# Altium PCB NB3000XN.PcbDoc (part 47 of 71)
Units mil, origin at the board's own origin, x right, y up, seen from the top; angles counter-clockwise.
Board outline 9527.56 x 6929.77 mil, 6 copper layers (Top Layer, GND+SHIELD, MidLayer1, MidLayer2, P2 - 3V3+5V0, Bottom Layer), stack 62.375 mil thick; 832 components, 1027 nets, 4655 pads, 4981 vias.
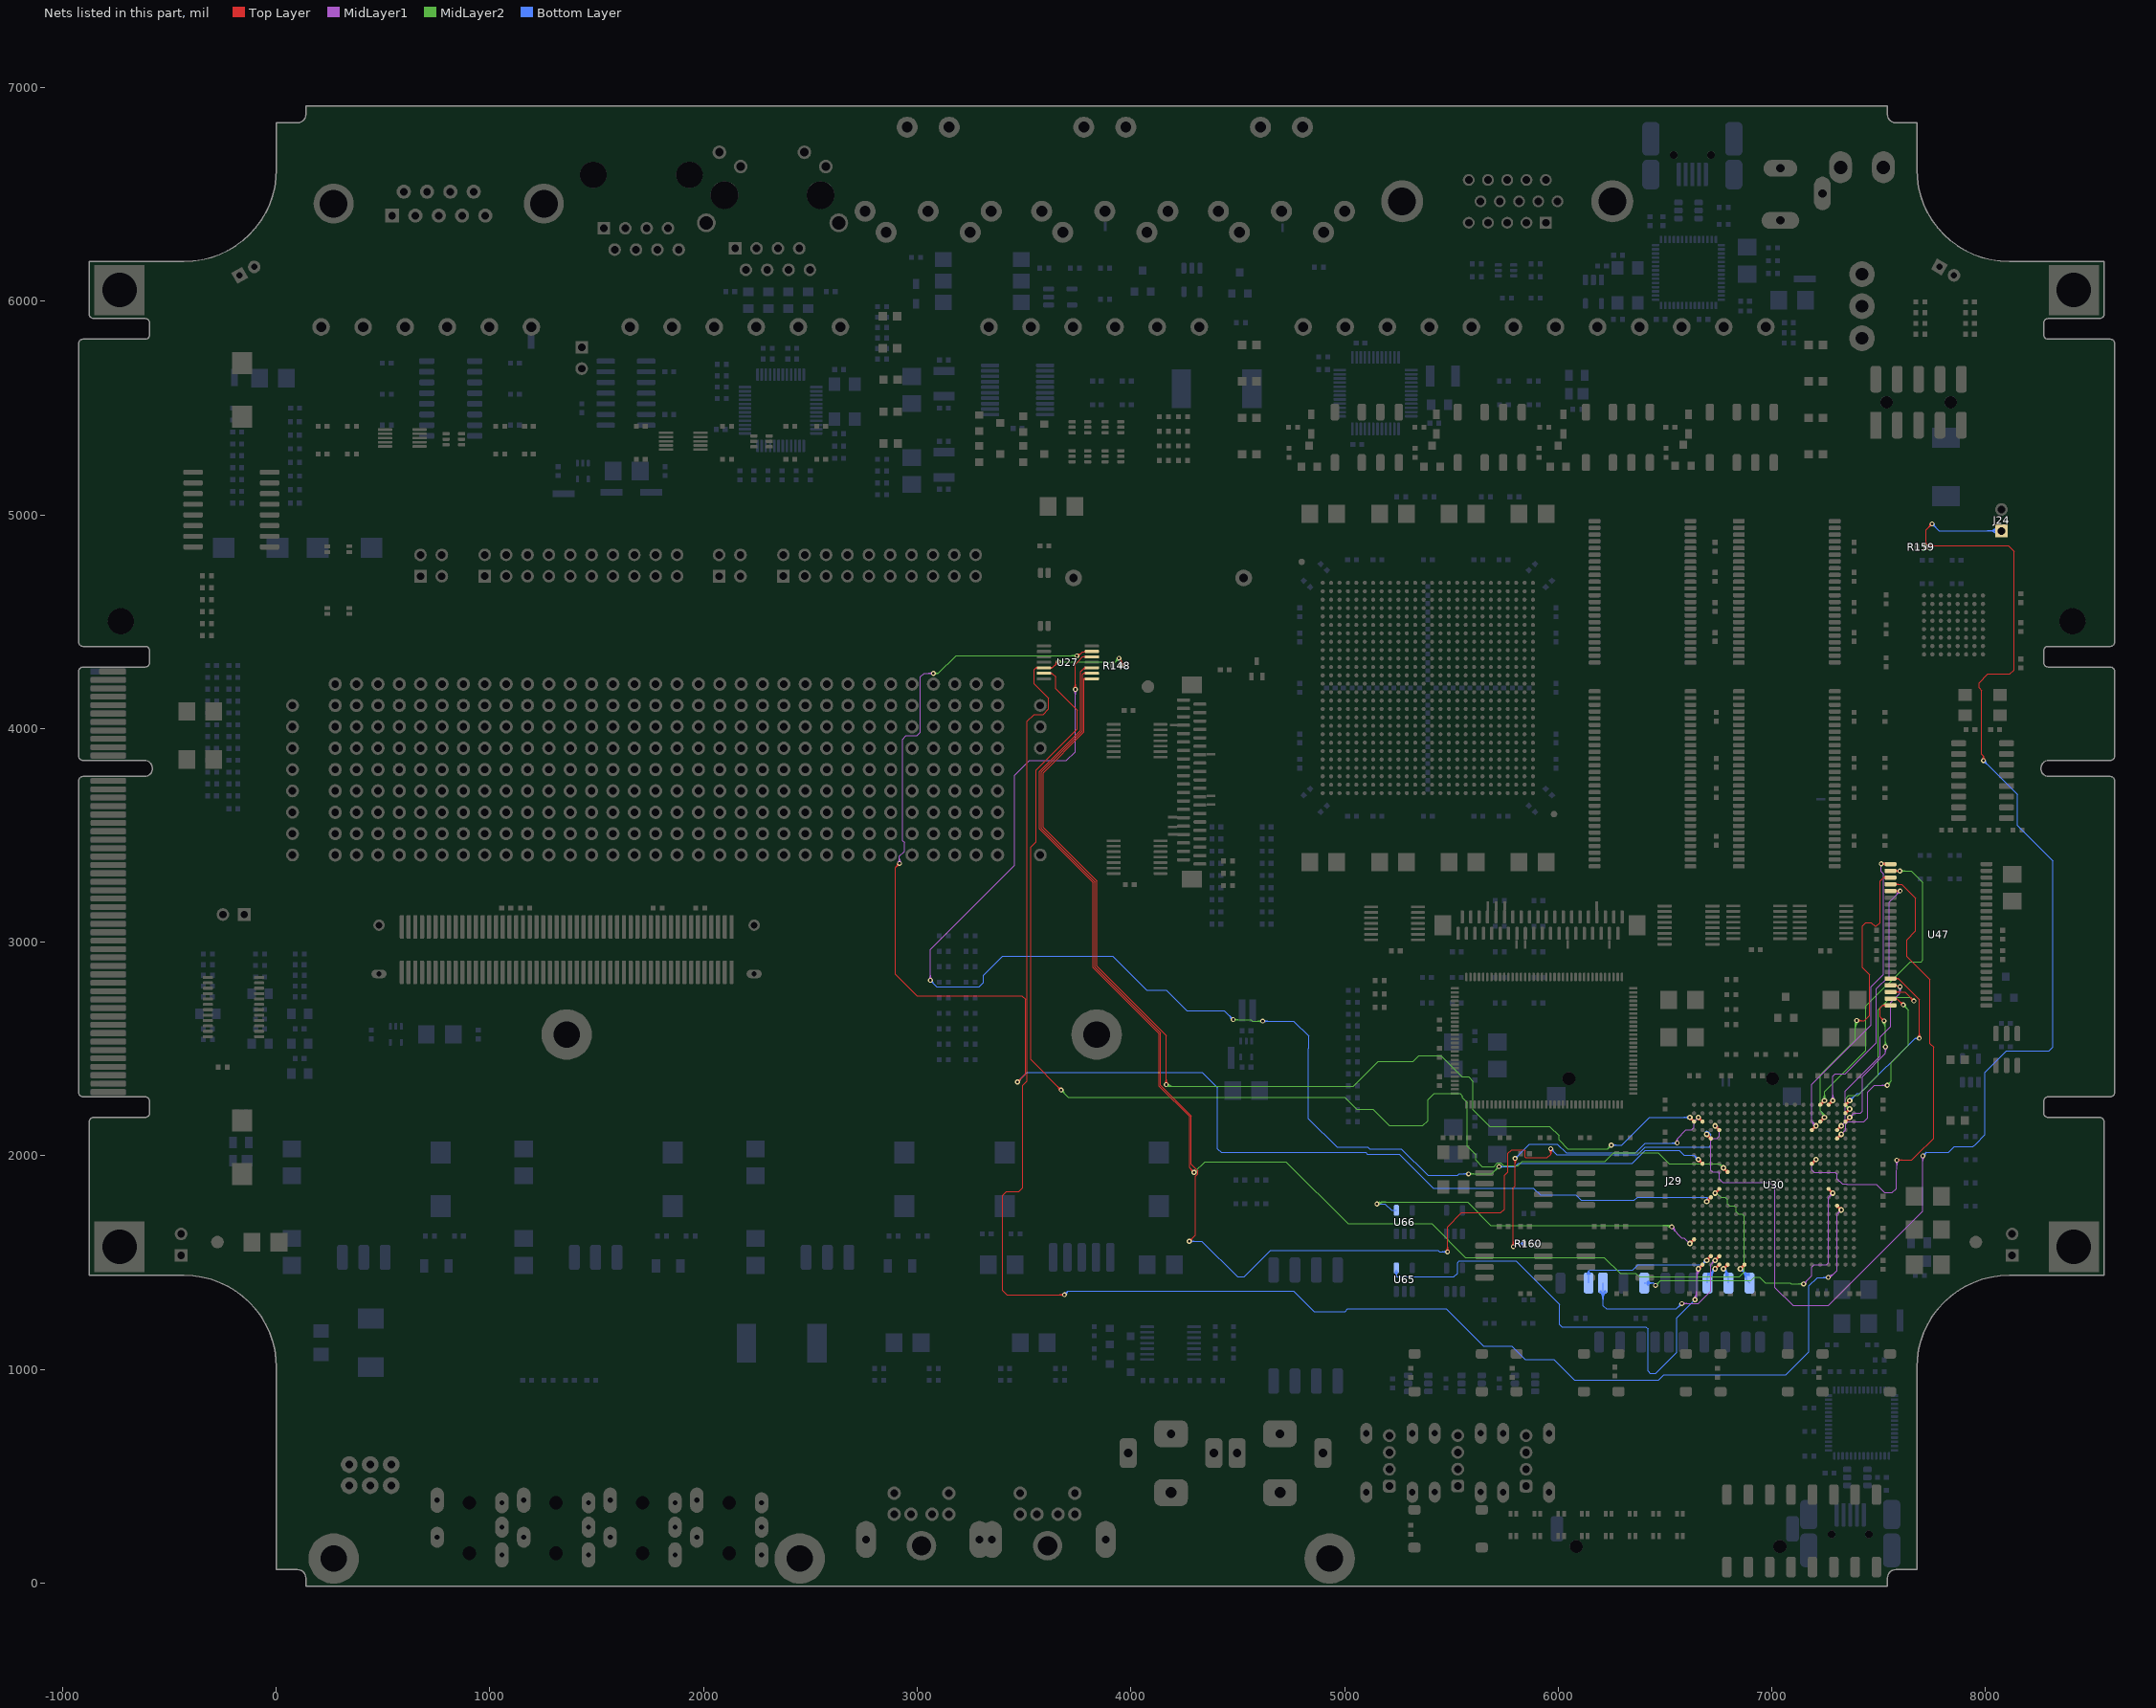
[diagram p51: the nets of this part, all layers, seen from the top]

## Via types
v1: diameter 23, hole 11.81, Top Layer to Bottom Layer, 3672 vias
v2: diameter 26, hole 11.81, Top Layer to Bottom Layer, 461 vias
v3: diameter 19, hole 11.81, Top Layer to Bottom Layer, tented both sides, 396 vias
v4: diameter 23.62, hole 11.81, Top Layer to Bottom Layer, 288 vias
v5: diameter 20, hole 11.81, Top Layer to Bottom Layer, 91 vias
v6: diameter 23, hole 11.81, Top Layer to Bottom Layer, tented both sides, 50 vias
v7: diameter 31, hole 11.81, Top Layer to Bottom Layer, 15 vias
v8: diameter 27.56, hole 11.81, Top Layer to Bottom Layer, tented both sides, 4 vias
v9: diameter 29, hole 11.81, Top Layer to Bottom Layer, 3 vias
v10: diameter 21, hole 11.81, Top Layer to Bottom Layer, 1 vias

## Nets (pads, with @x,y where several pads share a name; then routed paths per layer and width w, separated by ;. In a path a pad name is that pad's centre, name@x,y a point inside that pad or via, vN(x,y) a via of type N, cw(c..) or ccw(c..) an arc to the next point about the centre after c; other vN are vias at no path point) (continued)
HOST_M1: J24.1 R159.1 U30.U4 | length 7649.8
  Top Layer w4: R159.1@7714.59,4857.08 ccw(c7698.68,4872.99) 7721.18,4872.99 ccw(c7743.68,4872.99) R159.1@7727.77,4857.08 ; R159.1@7717.42,4854.25 ccw(c7708.34,4863.33) 7721.18,4863.33 ccw(c7734.02,4863.33) R159.1@7724.94,4854.25 ; R159.1@7722.11,4849.56 cw(c7740.08,4831.6) 7740.08,4857 ; R159.1@7724.94,4846.73 cw(c7749.73,4821.94) 7749.73,4857 ; R159.1@7727.77,4843.9 cw(c7759.39,4812.28) 7759.39,4857 ; v1@7740.69,4958.37 cw(c7717.76,4958.37) 7733.97,4942.16 cw(c7750.19,4925.94) v1@7750.19,4948.87 ; v1@7744.69,4958.37 cw(c7731.41,4958.37) 7740.8,4948.99 cw(c7750.19,4939.6) v1@7750.19,4952.87 ; v1(7750.19,4958.37) 7721.18,4929.37 R159.1@7721.18,4850 7728.18,4857 8107.71,4857 8135,4829.71 8135,4275 8115,4255 8011.82,4255 7970.52,4213.71 7970.52,4190 7981.86,4178.67 7981.86,3880 7990.19,3871.67 ; v1@7983.76,3857.04 ccw(c7970.33,3871.67) 7990.19,3871.67 ; v1@7986.47,3854.09 ccw(c7978.69,3862.56) 7990.19,3862.56 ccw(c8001.69,3862.56) v1@7993.91,3854.09 ; v1(7990.19,3850.04) 7990.19,3871.67 ; v1@7996.62,3857.04 cw(c8010.05,3871.67) 7990.19,3871.67
  Top Layer w8: v2@6734.41,2131.59 cw(c6734.41,2109.86) 6749.77,2125.23 cw(c6765.14,2140.59) v2@6743.41,2140.59 ; v2(6734.41,2140.59) U30.U4@6754.09,2120.91 ; U30.U4@6748.25,2120.91 ccw(c6734.15,2120.91) 6744.12,2130.88 ccw(c6754.09,2140.85) U30.U4@6754.09,2126.75
  MidLayer1 w4: v2@6734.41,2129.59 cw(c6734.41,2103.03) 6753.19,2121.81 cw(c6771.96,2140.59) v2@6745.41,2140.59 ; v2@6734.41,2133.59 cw(c6734.41,2116.69) 6746.36,2128.64 cw(c6758.31,2140.59) v2@6741.41,2140.59 ; v2(6734.41,2140.59) 6753.52,2121.48 6753.52,2091.71 6743.19,2081.37 6726.86,2081.37 6715.19,2069.71 6715.19,1932.37 6723.52,1924.04 6751.86,1924.04 6754.19,1921.71 6754.19,1891.71 6770.86,1875.04 6990.19,1875.04 7015.19,1850.04 7015.19,1383.37 7098.52,1300.04 7265.19,1300.04 7706.86,1741.71 v1(7706.86,2000.04) ; v1@7700.14,1993.32 cw(c7683.92,1977.11) 7706.86,1977.11 cw(c7729.79,1977.11) v1@7713.57,1993.32 ; v1@7702.97,1996.15 cw(c7693.58,1986.76) 7706.86,1986.76 cw(c7720.14,1986.76) v1@7710.75,1996.15
  Bottom Layer w4: v1(7706.86,2000.04) 7723.52,2016.71 7827.77,2016.71 7853.56,2042.5 7940.98,2042.5 7954.24,2055.76 7998.52,2100.04 7998.52,2391.71 8098.52,2491.71 8298.52,2491.71 8315.19,2508.37 8315.19,3380.39 8148.86,3546.73 8148.86,3691.37 8023.52,3816.71 v1(7990.19,3850.04) ; v1@7706.86,2005.54 ccw(c7706.86,2018.82) 7716.25,2009.43 ccw(c7725.64,2000.04) v1@7712.36,2000.04 ; v1@7706.86,2009.54 ccw(c7706.86,2032.48) 7723.07,2016.26 ccw(c7739.29,2000.04) v1@7716.36,2000.04 ; v1@7750.19,4948.87 cw(c7750.19,4925.94) 7766.41,4942.16 cw(c7782.63,4958.37) v1@7759.69,4958.37 ; v1@7750.19,4952.87 cw(c7750.19,4939.6) 7759.58,4948.99 cw(c7768.97,4958.37) v1@7755.69,4958.37 ; v1(7750.19,4958.37) 7783.19,4925.38 J24.1@8074.71,4925.38 ; v1@7990.19,3840.54 cw(c7990.19,3817.61) 8006.41,3833.82 cw(c8022.63,3850.04) v1@7999.69,3850.04 ; v1@7990.19,3844.54 cw(c7990.19,3831.26) 7999.58,3840.65 cw(c8008.97,3850.04) v1@7995.69,3850.04 ; J24.1@8055.24,4905.91 ccw(c8008.25,4858.92) 8008.25,4925.38 ccw(c8008.25,4991.84) J24.1@8055.24,4944.84 ; J24.1@8058.07,4908.74 ccw(c8017.91,4868.58) 8017.91,4925.38 ccw(c8017.91,4982.18) J24.1@8058.07,4942.01 ; J24.1@8060.9,4911.57 ccw(c8027.57,4878.23) 8027.57,4925.38 ccw(c8027.56,4972.52) J24.1@8060.9,4939.19 ; J24.1@8063.73,4914.4 ccw(c8037.22,4887.89) 8037.22,4925.38 ccw(c8037.22,4962.86) J24.1@8063.73,4936.36
HOST_M2: R160.1 U30.W3 | length 1865.2
  Top Layer w4: v1@5783.47,1581.76 ccw(c5767.26,1597.98) 5790.19,1597.98 ccw(c5813.13,1597.98) v1@5796.91,1581.76 ; v1@5786.3,1578.93 ccw(c5776.91,1588.32) 5790.19,1588.32 ccw(c5803.47,1588.32) v1@5794.08,1578.93 ; v1(5790.19,1575.04) 5790.19,1850.04 5798.52,1858.37 v1(5798.52,1988.04) ; v1@5791.81,1981.32 cw(c5775.59,1965.11) 5798.52,1965.11 cw(c5821.46,1965.11) v1@5805.24,1981.32 ; v1@5794.64,1984.15 cw(c5785.25,1974.76) 5798.52,1974.76 cw(c5811.8,1974.76) v1@5802.41,1984.15
  Top Layer w8: v2@6655.67,2170.96 cw(c6655.67,2149.23) 6671.03,2164.6 cw(c6686.4,2179.96) v2@6664.67,2179.96 ; v2(6655.67,2179.96) U30.W3@6675.35,2160.28 ; U30.W3@6669.51,2160.28 ccw(c6655.41,2160.28) 6665.38,2170.25 ccw(c6675.35,2180.22) U30.W3@6675.35,2166.12
  MidLayer1 w4: v1@6551.05,2067.56 ccw(c6541.94,2079.37) 6556.86,2079.37 ; v1(6556.86,2060.04) 6556.86,2079.37 ; v1@6562.66,2067.56 cw(c6571.78,2079.37) 6556.86,2079.37 ; v2(6655.67,2179.96) 6640.19,2164.48 6640.19,2163.48 6638.52,2161.82 6637.52,2161.82 6636.52,2160.82 6636.52,2133.37 6624.19,2121.04 6598.52,2121.04 6556.86,2079.37
  Bottom Layer w4: v1(5790.19,1575.04) 5805.15,1590 R160.1@5839.87,1590 ; v1(5798.52,1988.04) 5843.85,2033.36 5865.48,2055 5996.25,2055 6037.06,2014.19 6362.67,2014.19 6364.86,2016.37 6408.52,2060.04 v1(6556.86,2060.04) ; v1@5798.52,1993.54 ccw(c5798.52,2006.82) 5807.91,1997.43 ccw(c5817.3,1988.04) v1@5804.02,1988.04 ; v1@5798.52,1997.54 ccw(c5798.52,2020.48) 5814.74,2004.26 ccw(c5830.96,1988.04) v1@5808.02,1988.04 ; R160.1@5833.29,1583.41 ccw(c5817.38,1567.5) 5817.38,1590 ccw(c5817.38,1612.5) R160.1@5833.29,1596.59 ; R160.1@5836.11,1586.24 ccw(c5827.03,1577.16) 5827.03,1590 ccw(c5827.03,1602.84) R160.1@5836.11,1593.76 ; v1@6550.14,2053.32 ccw(c6533.92,2037.11) 6533.92,2060.04 ccw(c6533.92,2082.98) v1@6550.14,2066.76 ; v1@6552.97,2056.15 ccw(c6543.58,2046.76) 6543.58,2060.04 ccw(c6543.58,2073.32) v1@6552.97,2063.93
HOST_RTC.CLKOE: U27.12 U30.W8 | length 7212.1
  Top Layer w4: v1@3733.47,4190.09 ccw(c3717.26,4206.31) 3740.19,4206.31 ccw(c3763.13,4206.31) v1@3746.91,4190.09 ; v1@3736.3,4187.26 ccw(c3726.91,4196.65) 3740.19,4196.65 ccw(c3753.47,4196.65) v1@3744.08,4187.26 ; v1(3740.19,4183.37) 3740.19,4300.78 3754.62,4315.21 3775,4335.59 U27.12@3817.2,4335.59 ; U27.12@3787.17,4332.13 ccw(c3778.82,4323.79) 3778.82,4335.59 ccw(c3778.83,4347.39) U27.12@3787.17,4339.05
  Top Layer w8: v2@6655.67,1974.11 cw(c6655.67,1952.38) 6671.03,1967.75 cw(c6686.4,1983.11) v2@6664.67,1983.11 ; v2(6655.67,1983.11) U30.W8@6675.35,1963.43 ; U30.W8@6669.51,1963.43 ccw(c6655.41,1963.43) 6665.38,1973.4 ccw(c6675.35,1983.37) U30.W8@6675.35,1969.27
  MidLayer1 w4: v1@3054.81,2828.43 ccw(c3038.59,2844.64) 3061.52,2844.64 ccw(c3084.46,2844.64) v1@3068.24,2828.43 ; v1@3057.64,2825.6 ccw(c3048.25,2834.99) 3061.52,2834.99 ccw(c3074.8,2834.99) v1@3065.41,2825.6 ; v1(3061.52,2821.71) 3061.52,2966.02 3456.86,3361.36 3456.86,3781 3525.9,3850.04 3698.52,3850.04 3740.19,3891.71 v1(3740.19,4183.37) ; v1@3733.47,4176.66 cw(c3717.26,4160.44) 3740.19,4160.44 cw(c3763.13,4160.44) v1@3746.91,4176.66 ; v1@3736.3,4179.49 cw(c3726.91,4170.1) 3740.19,4170.1 cw(c3753.47,4170.1) v1@3744.08,4179.49
  MidLayer2 w4: v1(4478.86,2638.04) 4563,2638.04 4570,2631.04 v1(4616.86,2631.04) ; v1@4482.75,2634.15 cw(c4492.14,2624.76) 4492.14,2638.04 cw(c4492.14,2651.32) v1@4482.75,2641.93 ; v1@4485.57,2631.32 cw(c4501.79,2615.11) 4501.79,2638.04 cw(c4501.79,2660.98) v1@4485.57,2644.76 ; v1@4610.14,2624.32 ccw(c4593.92,2608.11) 4593.92,2631.04 ccw(c4593.92,2653.98) v1@4610.14,2637.76 ; v1@4612.97,2627.15 ccw(c4603.58,2617.76) 4603.58,2631.04 ccw(c4603.58,2644.32) v1@4612.97,2634.93 ; v1@5580.6,1913.79 v1(5580.6,1915.37) 5688.85,1915.37 v1(5723.52,1950.04) ; v1@5584.49,1911.48 cw(c5593.88,1902.09) 5593.88,1915.37 cw(c5593.88,1928.65) v1@5584.49,1919.26 ; v1@5587.32,1908.65 cw(c5603.54,1892.43) 5603.54,1915.37 cw(c5603.54,1938.3) v1@5587.32,1922.09 ; v1@5714.02,1950.04 cw(c5691.09,1950.04) 5707.31,1933.82 cw(c5723.52,1917.61) v1@5723.52,1940.54 ; v1@5718.02,1950.04 cw(c5704.75,1950.04) 5714.14,1940.65 cw(c5723.52,1931.26) v1@5723.52,1944.54
  Bottom Layer w4: v1@3061.52,2812.21 cw(c3061.52,2789.27) 3077.74,2805.49 cw(c3093.96,2821.71) v1@3071.02,2821.71 ; v1@3061.52,2816.21 cw(c3061.52,2802.93) 3070.91,2812.32 cw(c3080.3,2821.71) v1@3067.02,2821.71 ; v1(3061.52,2821.71) 3091.52,2791.71 3290.19,2791.71 3310.81,2812.32 3310.81,2845.81 3399.37,2934.37 3914.19,2934.37 4073.52,2775.04 4165.19,2775.04 4261.19,2679.04 4437.86,2679.04 v1(4478.86,2638.04) ; v1@4469.36,2638.04 ccw(c4446.42,2638.04) 4462.64,2654.26 ccw(c4478.86,2670.48) v1@4478.86,2647.54 ; v1@4473.36,2638.04 ccw(c4460.08,2638.04) 4469.47,2647.43 ccw(c4478.86,2656.82) v1@4478.86,2643.54 ; v1(4616.86,2631.04) 4761.56,2631.04 4832.19,2560.41 4832.19,2502.81 ; v1@4620.75,2627.15 cw(c4630.14,2617.76) 4630.14,2631.04 cw(c4630.14,2644.32) v1@4620.75,2634.93 ; v1@4623.57,2624.32 cw(c4639.79,2608.11) 4639.79,2631.04 cw(c4639.79,2653.98) v1@4623.57,2637.76 ; 4831.86,2502.81 4831.86,2174.04 4964.19,2041.71 5108.19,2041.71 5116.52,2033.37 5266.15,2033.37 5391.15,1908.37 5530,1908.37 5536.99,1915.37 v1(5580.6,1915.37) v1@5580.6,1913.79 ; v1@5573.88,1908.65 ccw(c5557.67,1892.43) 5557.67,1915.37 ccw(c5557.67,1938.3) v1@5573.88,1922.09 ; v1@5576.71,1911.48 ccw(c5567.32,1902.09) 5567.32,1915.37 ccw(c5567.32,1928.65) v1@5576.71,1919.26 ; v1(5723.52,1950.04) 5798.52,1950.04 5814.52,1966.04 6347.86,1966.04 6406.86,2025.04 6567.52,2025.04 6589.86,2002.71 6636.07,2002.71 v2(6655.67,1983.11) ; v1@5727.41,1946.15 cw(c5736.8,1936.76) 5736.8,1950.04 cw(c5736.8,1963.32) v1@5727.41,1953.93 ; v1@5730.24,1943.32 cw(c5746.46,1927.11) 5746.46,1950.04 cw(c5746.46,1972.98) v1@5730.24,1956.76 ; v2@6644.67,1983.11 ccw(c6618.11,1983.11) 6636.89,2001.89 ccw(c6655.67,2020.67) v2@6655.67,1994.11 ; v2@6648.67,1983.11 ccw(c6631.77,1983.11) 6643.72,1995.06 ccw(c6655.67,2007.01) v2@6655.67,1990.11
HOST_RTC.CLKOUT: U27.13 U30.V12 | length 7676.6
  Top Layer w4: v1@2907.69,3368.71 cw(c2884.76,3368.71) 2900.97,3352.49 cw(c2917.19,3336.27) v1@2917.19,3359.21 ; v1@2911.69,3368.71 cw(c2898.41,3368.71) 2907.8,3359.32 cw(c2917.19,3349.93) v1@2917.19,3363.21 ; v1(2917.19,3368.71) 2898.52,3350.04 2898.52,2850.04 2999.02,2749.54 3490.46,2749.54 3507.19,2732.81 3507.19,2383.71 v1(3469.52,2346.04) ; v1@3469.52,2351.54 ccw(c3469.52,2364.82) 3478.91,2355.43 ccw(c3488.3,2346.04) v1@3475.02,2346.04 ; v1@3469.52,2355.54 ccw(c3469.52,2378.48) 3485.74,2362.26 ccw(c3501.96,2346.04) v1@3479.02,2346.04 ; v1(3747.52,4340.37) 3755.52,4340.37 3773.52,4358.37 ; v1@3747.71,4341.86 ccw(c3749.78,4358.89) 3761.91,4346.76 ; v1@3748.19,4345.83 ccw(c3751.04,4369.24) 3767.72,4352.57 ; v1@3748.67,4349.81 ccw(c3752.3,4379.59) 3773.52,4358.37 ; 3782.42,4358.37 ccw(c3782.42,4368.46) U27.13@3789.96,4361.77 ; U27.13@3786.97,4364.42 cw(c3773.53,4376.34) 3773.53,4358.37 ; U27.13@3817.2,4361.18 3790.63,4361.17 3790.63,4358.37 3773.52,4358.37
  Top Layer w8: v2(6695.04,1786.26) U30.V12@6714.72,1805.94 ; v2@6695.04,1795.26 ccw(c6695.04,1816.99) 6710.4,1801.62 ccw(c6725.77,1786.26) v2@6704.04,1786.26 ; U30.V12@6708.88,1805.94 cw(c6694.78,1805.94) 6704.75,1795.97 cw(c6714.72,1786) U30.V12@6714.72,1800.1
  MidLayer1 w4: v1@2910.47,3375.43 ccw(c2894.26,3391.64) 2917.19,3391.64 ccw(c2940.13,3391.64) v1@2923.91,3375.43 ; v1@2913.3,3372.6 ccw(c2903.91,3381.99) 2917.19,3381.99 ccw(c2930.47,3381.99) v1@2921.08,3372.6 ; v1(2917.19,3368.71) 2917.19,3402.04 2940.19,3425.04 2940.19,3466.71 2931.86,3475.04 2931.86,3950.04 2948.52,3966.71 2998.52,3966.71 3015.19,3983.37 3015.19,4241.71 3031.86,4258.37 v1(3075.86,4258.37) ; v1@3069.14,4251.66 ccw(c3052.92,4235.44) 3052.92,4258.37 ccw(c3052.92,4281.31) v1@3069.14,4265.09 ; v1@3071.97,4254.49 ccw(c3062.58,4245.1) 3062.58,4258.37 ccw(c3062.58,4271.65) v1@3071.97,4262.26
  MidLayer2 w4: v1(3075.86,4258.37) 3098.52,4258.37 ; v1@3079.78,4254.52 cw(c3088.98,4245.47) 3088.98,4258.37 cw(c3088.98,4271.28) v1@3079.78,4262.23 ; v1@3082.63,4251.71 cw(c3098.52,4236.09) 3098.52,4258.37 ; v1@3082.63,4265.04 ccw(c3098.52,4280.66) 3098.52,4258.37 ; 3721.37,4341.71 cw(c3721.37,4314.22) v1@3740.81,4333.66 ; 3727.81,4341.71 ccw(c3727.81,4360.09) v1@3740.81,4347.09 ; 3731.03,4341.71 cw(c3731.03,4323.88) v1@3743.64,4336.49 ; v1(3747.52,4340.37) 3746.19,4341.71 3181.86,4341.71 3098.52,4258.37
  Bottom Layer w4: v1(3469.52,2346.04) 3515.19,2391.71 4334.84,2391.71 4406.52,2320.02 4406.52,2033.16 4422.98,2016.71 5099.25,2016.71 5107.25,2008.71 5256.52,2008.71 5277.07,1988.16 5415.52,1849.71 5883.17,1849.71 5916.17,1816.71 6081.86,1816.71 6106.86,1791.71 6356.86,1791.71 6371.52,1806.37 6696.86,1806.37 6698.52,1804.71 ; v1@3469.52,2351.54 ccw(c3469.52,2364.82) 3478.91,2355.43 ccw(c3488.3,2346.04) v1@3475.02,2346.04 ; v1@3469.52,2355.54 ccw(c3469.52,2378.48) 3485.74,2362.26 ccw(c3501.96,2346.04) v1@3479.02,2346.04 ; v2@6692.43,1796.95 ccw(c6690.53,1804.71) 6698.52,1804.71 ; v2@6693.38,1793.06 ccw(c6691.78,1799.61) 6698.52,1799.61 ; v2(6695.04,1786.26) 6698.52,1786.26 6698.52,1804.71 ; 6698.52,1804.4 ccw(c6713.18,1804.4) v2@6702.82,1794.04
HOST_RTC.CS_N: U27.6 U30.T9 | length 6107.5
  Top Layer w4: U27.6@3592.8,4258.82 3631.41,4258.82 3648.52,4241.71 3648.52,4186.73 3749.19,4086.06 3749.19,3998.34 3557.19,3806.34 3557.19,3470.33 3531.86,3445 3531.86,2450.04 v1(3673.52,2308.37) ; U27.6@3622.83,4255.36 cw(c3631.17,4247.01) 3631.17,4258.82 cw(c3631.18,4270.62) U27.6@3622.83,4262.28 ; v1@3664.02,2308.37 ccw(c3641.09,2308.37) 3657.31,2324.59 ccw(c3673.52,2340.81) v1@3673.52,2317.87 ; v1@3668.02,2308.37 ccw(c3654.75,2308.37) 3664.14,2317.76 ccw(c3673.52,2327.15) v1@3673.52,2313.87
  Top Layer w8: v2@6773.78,1934.74 cw(c6773.78,1913.01) 6789.14,1928.38 cw(c6804.51,1943.74) v2@6782.78,1943.74 ; v2(6773.78,1943.74) U30.T9@6793.46,1924.06 ; U30.T9@6787.62,1924.06 ccw(c6773.52,1924.06) 6783.49,1934.03 ccw(c6793.46,1944) U30.T9@6793.46,1929.9
  MidLayer2 w4: v1@3673.52,2298.87 cw(c3673.52,2275.94) 3689.74,2292.16 cw(c3705.96,2308.37) v1@3683.02,2308.37 ; v1@3673.52,2302.87 cw(c3673.52,2289.6) 3682.91,2298.99 cw(c3692.3,2308.37) v1@3679.02,2308.37 ; v1(3673.52,2308.37) 3707.19,2274.71 5001.84,2274.71 5057.53,2219.02 5132.88,2219.02 5210.19,2141.71 5366.9,2141.71 5390.19,2165 5390.19,2263.04 5418.86,2291.71 5540.19,2291.71 5552.19,2279.71 5552.19,2272.62 5575,2249.81 5575,2045 5614.02,2005.98 5614.02,1980 5644.02,1950 5698.73,1950 5716.28,1967.54 5730.77,1967.54 5743.77,1954.54 5812.4,1954.54 5831.57,1973.71 6219.57,1973.71 6260.05,2014.19 6467.71,2014.19 6518.86,1963.04 6754.48,1963.04 v2(6773.78,1943.74) ; v2@6762.78,1943.74 ccw(c6736.22,1943.74) 6755,1962.52 ccw(c6773.78,1981.3) v2@6773.78,1954.74 ; v2@6766.78,1943.74 ccw(c6749.88,1943.74) 6761.83,1955.69 ccw(c6773.78,1967.64) v2@6773.78,1950.74
HOST_RTC.DIN: U27.9 U30.V5 | length 6833.9
  Top Layer w4: U27.9@3787.17,4255.36 ccw(c3778.83,4247.01) 3778.83,4258.82 ; U27.9@3787.17,4262.28 cw(c3778.82,4270.62) 3778.82,4258.82 ; U27.9@3817.2,4258.82 3778.82,4258.82 ; v1(4273.52,1600.04) 4303.2,1629.72 4303.2,1905.16 4313.46,1915.41 4313.46,1929.91 4282.52,1960.84 4282.52,2187.48 4140,2330 4140,2575.9 3832,2883.9 3832,3282.56 3581.19,3533.37 3581.19,3796.39 3773.52,3988.73 3773.52,4253.52 3778.82,4258.82 ; v1@4273.52,1605.54 ccw(c4273.52,1618.82) 4282.91,1609.43 ccw(c4292.3,1600.04) v1@4279.02,1600.04 ; v1@4273.52,1609.54 ccw(c4273.52,1632.48) 4289.74,1616.26 ccw(c4305.96,1600.04) v1@4283.02,1600.04 ; v1(5481.86,1550.04) 5481.86,1666.71 5548.52,1733.37 5731.86,1733.37 5748.52,1750.04 5748.52,1908.37 5765.19,1925.04 5765.19,2011.71 5781.86,2028.37 5843.86,2028.37 5845.52,2026.71 5845.52,1993.37 5847.19,1991.71 5948.52,1991.71 5965.19,2008.37 v1(5965.19,2033.37) ; v1@5958.47,2026.66 cw(c5942.26,2010.44) 5965.19,2010.44 cw(c5988.13,2010.44) v1@5971.91,2026.66 ; v1@5961.3,2029.49 cw(c5951.91,2020.1) 5965.19,2020.1 cw(c5978.47,2020.1) v1@5969.08,2029.49 ; 5481.86,1563.32 cw(c5468.58,1563.32) 5477.97,1553.93 ccw(c5468.58,1563.32) 5481.86,1563.32 ; 5481.86,1563.32 ccw(c5495.14,1563.32) 5485.75,1553.93 cw(c5495.14,1563.32) 5481.86,1563.32 ; 5481.86,1572.98 cw(c5458.92,1572.98) 5475.14,1556.76 ccw(c5458.92,1572.98) 5481.86,1572.98 ; 5481.86,1572.98 ccw(c5504.79,1572.98) 5488.57,1556.76 cw(c5504.79,1572.98) 5481.86,1572.98
  Top Layer w8: v2@6695.04,2092.22 cw(c6695.04,2070.49) 6710.4,2085.86 cw(c6725.77,2101.22) v2@6704.04,2101.22 ; v2(6695.04,2101.22) U30.V5@6714.72,2081.54 ; U30.V5@6708.88,2081.54 ccw(c6694.78,2081.54) 6704.75,2091.51 ccw(c6714.72,2101.48) U30.V5@6714.72,2087.38
  Bottom Layer w4: v1(4273.52,1600.04) 4331.86,1600.04 4498.52,1433.37 4530,1433.37 4600.69,1504.06 4653.63,1557 5438,1557 5444.96,1550.04 v1(5481.86,1550.04) ; v1@4277.41,1596.15 cw(c4286.8,1586.76) 4286.8,1600.04 cw(c4286.8,1613.32) v1@4277.41,1603.93 ; v1@4280.24,1593.32 cw(c4296.46,1577.11) 4296.46,1600.04 cw(c4296.46,1622.98) v1@4280.24,1606.76 ; v1@5475.14,1543.32 ccw(c5458.92,1527.11) 5458.92,1550.04 ccw(c5458.92,1572.98) v1@5475.14,1556.76 ; v1@5477.97,1546.15 ccw(c5468.58,1536.76) 5468.58,1550.04 ccw(c5468.58,1563.32) v1@5477.97,1553.93 ; v1@5965.19,2023.87 cw(c5965.19,2000.94) 5981.41,2017.16 cw(c5997.63,2033.37) v1@5974.69,2033.37 ; v1@5965.19,2027.87 cw(c5965.19,2014.6) 5974.58,2023.99 cw(c5983.97,2033.37) v1@5970.69,2033.37 ; v1(5965.19,2033.37) 5992.38,2006.19 6371.34,2006.19 6406.86,2041.71 6706.86,2041.71 6715.19,2050.04 6715.19,2100.04 6706.86,2108.37 6695.04,2108.37 v2(6695.04,2101.22) ; 6687.37,2111.71 cw(c6695.33,2100.82) 6704.87,2110.36 ; v2@6689.73,2108.49 cw(c6698.12,2097.01) 6708.17,2107.06 ; v2@6692.09,2105.26 cw(c6700.91,2093.2) 6711.47,2103.76 ; v2@6694.45,2102.03 cw(c6703.7,2089.38) 6714.77,2100.46
HOST_RTC.DOUT: U27.8 U30.Y3 | length 5564
  Top Layer w4: U27.8@3786.55,4230.53 ccw(c3781.52,4227.19) 3781.52,4233.23 ; U27.8@3786.55,4235.93 cw(c3781.52,4239.26) 3781.52,4233.23 ; U27.8@3817.2,4233.23 3781.52,4233.23 ; 3840,3205 3840,3285.88 3589.19,3536.69 3589.19,3793.08 3781.52,3985.41 3781.52,4233.23 ; 3840.19,3205 3840.19,2887.02 4165.19,2562.02 v1(4165.19,2333.37) ; v1@4158.47,2340.09 ccw(c4142.26,2356.31) 4165.19,2356.31 ccw(c4188.13,2356.31) v1@4171.91,2340.09 ; v1@4161.3,2337.26 ccw(c4151.91,2346.65) 4165.19,2346.65 ccw(c4178.47,2346.65) v1@4169.08,2337.26
  Top Layer w8: v2@6616.3,2170.96 cw(c6616.3,2149.23) 6631.66,2164.6 cw(c6647.03,2179.96) v2@6625.3,2179.96 ; v2(6616.3,2179.96) U30.Y3@6635.98,2160.28 ; U30.Y3@6630.14,2160.28 ccw(c6616.04,2160.28) 6626.01,2170.25 ccw(c6635.98,2180.22) U30.Y3@6635.98,2166.12
  MidLayer2 w4: v1@4163.42,2331.61 ccw(c4179.27,2347.46) 4179.27,2325.04 ; v1(4165.19,2333.37) 4173.52,2325.04 5041.35,2325.04 5158.02,2441.71 5321.52,2441.71 5348.52,2468.71 5451.29,2468.71 5550,2370 5580,2370 5602.19,2347.81 5602.19,2275 ; v1@4166.25,2334.44 ccw(c4188.93,2357.12) 4188.93,2325.04 ; v1@4169.08,2337.26 ccw(c4198.59,2366.77) 4198.59,2325.04 ; v1@4171.91,2340.09 ccw(c4208.25,2376.43) 4208.25,2325.04 ; 5602.19,2290 5602.19,2275 ; v1@6239.02,2050.04 cw(c6216.09,2050.04) 6232.31,2033.82 cw(c6248.52,2017.61) v1@6248.52,2040.54 ; v1@6243.02,2050.04 cw(c6229.75,2050.04) 6239.13,2040.65 cw(c6248.52,2031.26) v1@6248.52,2044.54 ; v1(6248.52,2050.04) 6231.86,2033.37 6045.56,2033.37 6004.5,2074.44 6004.5,2094.06 5960.19,2138.37 5678.81,2138.37 5602.19,2215 5602.19,2275
  Bottom Layer w4: v1(6248.52,2050.04) 6298.52,2050.04 6428.44,2179.96 v2(6616.3,2179.96) ; v1@6252.41,2046.15 cw(c6261.8,2036.76) 6261.8,2050.04 cw(c6261.8,2063.32) v1@6252.41,2053.93 ; v1@6255.24,2043.32 cw(c6271.46,2027.11) 6271.46,2050.04 cw(c6271.46,2072.98) v1@6255.24,2056.76 ; v2@6608.52,2172.18 ccw(c6589.74,2153.4) 6589.74,2179.96 ccw(c6589.74,2206.52) v2@6608.52,2187.74 ; v2@6611.35,2175.01 ccw(c6599.4,2163.06) 6599.4,2179.96 ccw(c6599.4,2196.86) v2@6611.35,2184.91
HOST_RTC.INT_N: R148.2 U27.5 U30.C13 | length 8985.1
  Top Layer w4: U27.5@3562.29,4281.5 ccw(c3556.52,4277.24) 3556.52,4284.41 ; U27.5@3562.29,4287.32 cw(c3556.52,4291.58) 3556.52,4284.41 ; U27.5@3622.83,4280.95 cw(c3631.17,4272.61) 3631.17,4284.41 cw(c3631.18,4296.22) U27.5@3622.83,4287.87 ; v1@3652.02,4312.37 cw(c3629.09,4312.37) 3645.31,4296.16 cw(c3661.52,4279.94) v1@3661.52,4302.87 ; v1@3656.02,4312.37 cw(c3642.75,4312.37) 3652.14,4302.99 cw(c3661.52,4293.6) v1@3661.52,4306.87 ; v1(3661.52,4312.37) 3633.56,4284.41 3556.52,4284.41 ; v1@3682.47,1343.32 ccw(c3666.26,1327.11) 3666.26,1350.04 ccw(c3666.26,1372.98) v1@3682.47,1356.76 ; v1@3685.3,1346.15 ccw(c3675.91,1336.76) 3675.91,1350.04 ccw(c3675.91,1363.32) v1@3685.3,1353.93 ; v1(3689.19,1350.04) 3419.96,1350.04 3400,1370 3400,1815 3418,1833 3476.69,1833 3495,1851.31 3495,2329.81 3515.19,2350 3515.19,4033.37 3548.52,4066.71 3590.19,4066.71 3615.19,4091.71 3615.19,4141.71 3548.52,4208.37 3548.52,4276.41 3556.52,4284.41 ; v1(3944.52,4329.37) 3956.18,4317.72 ; R148.2@3949.65,4302.14 ccw(c3934.34,4317.72) 3956.18,4317.72 ; R148.2@3952.45,4299.29 ccw(c3943.71,4308.18) 3956.18,4308.18 ccw(c3968.65,4308.18) R148.2@3959.91,4299.29 ; R148.2@3956.18,4295 3956.18,4317.72 ; R148.2@3962.71,4302.14 cw(c3978.02,4317.72) 3956.18,4317.72
  Top Layer w8: U30.C13@7305.28,1760.73 cw(c7305.28,1746.63) 7315.25,1756.6 cw(c7325.22,1766.57) U30.C13@7311.12,1766.57 ; U30.C13@7305.28,1766.57 v2(7324.96,1746.89) ; v2@7315.96,1746.89 ccw(c7294.23,1746.89) 7309.6,1762.25 ccw(c7324.96,1777.62) v2@7324.96,1755.89
  MidLayer1 w4: v1(7263.86,1431.04) 7272.2,1431.04 7305,1463.84 7305,1726.93 v2(7324.96,1746.89) ; v1@7263.86,1432.54 ccw(c7263.86,1456.31) 7280.66,1439.5 ; v1@7263.86,1436.54 ccw(c7263.86,1469.97) 7287.49,1446.33 ; v1@7263.86,1440.54 ccw(c7263.86,1483.62) 7294.32,1453.16 ; v2@7313.96,1746.89 cw(c7287.4,1746.89) 7306.18,1728.11 cw(c7324.96,1709.33) v2@7324.96,1735.89 ; v2@7317.96,1746.89 cw(c7301.06,1746.89) 7313.01,1734.94 cw(c7324.96,1722.99) v2@7324.96,1739.89
  MidLayer2 w4: v1(3661.52,4312.37) 3927.52,4312.37 v1(3944.52,4329.37) ; v1@3665.41,4308.49 cw(c3674.8,4299.1) 3674.8,4312.37 cw(c3674.8,4325.65) v1@3665.41,4316.26 ; v1@3668.24,4305.66 cw(c3684.46,4289.44) 3684.46,4312.37 cw(c3684.46,4335.31) v1@3668.24,4319.09 ; v1@3935.02,4329.37 cw(c3912.09,4329.37) 3928.31,4313.16 cw(c3944.52,4296.94) v1@3944.52,4319.87 ; v1@3939.02,4329.37 cw(c3925.75,4329.37) 3935.14,4319.99 cw(c3944.52,4310.6) v1@3944.52,4323.87
  Bottom Layer w4: v1(3689.19,1350.04) 3706.19,1367.04 4761.88,1367.04 4856.92,1272 5003.31,1272 5014.69,1283.37 5475.9,1283.37 5650.27,1109 5783.6,1109 5838.8,1053.8 5845.6,1047 5979.56,1047 6076.52,950.04 6469.82,950.04 6494.82,975.04 7065.04,975.04 7173.52,1083.52 7173.52,1391.71 7212.86,1431.04 v1(7263.86,1431.04) ; v1@3689.19,1355.54 ccw(c3689.19,1368.82) 3698.58,1359.43 ccw(c3707.97,1350.04) v1@3694.69,1350.04 ; v1@3689.19,1359.54 ccw(c3689.19,1382.48) 3705.41,1366.26 ccw(c3721.63,1350.04) v1@3698.69,1350.04 ; v1@7257.14,1424.32 ccw(c7240.92,1408.11) 7240.92,1431.04 ccw(c7240.92,1453.98) v1@7257.14,1437.76 ; v1@7259.97,1427.15 ccw(c7250.58,1417.76) 7250.58,1431.04 ccw(c7250.58,1444.32) v1@7259.97,1434.93
HOST_RTC.SCLK: U27.10 U30.U11 | length 6377.7
  Top Layer w4: 3769.07,4270.59 cw(c3790.63,4249.03) U27.10@3790.63,4279.52 ; 3775.9,4277.42 cw(c3790.63,4262.69) U27.10@3790.63,4283.52 ; 3777.99,4279.51 cw(c3783.45,4274.05) U27.10@3787.84,4280.39 ; 3781.38,4282.89 cw(c3786.22,4278.05) U27.10@3790.12,4283.68 ; 3782.73,4284.25 cw(c3790.63,4276.35) U27.10@3790.63,4287.52 ; U27.10@3786.09,4286.24 cw(c3781.86,4287.94) 3781.86,4283.37 ; U27.10@3787.03,4281.1 ccw(c3781.86,4276.36) 3781.86,4283.37 ; U27.10@3817.2,4284.41 3823.52,4284.41 3823.52,4283.37 3781.86,4283.37 ; v1@4286.46,1922.66 ccw(c4263.52,1922.66) 4279.74,1938.88 ccw(c4295.96,1955.1) v1@4295.96,1932.16 ; v1@4290.46,1922.66 ccw(c4277.18,1922.66) 4286.57,1932.05 ccw(c4295.96,1941.44) v1@4295.96,1928.16 ; v1(4295.96,1922.66) 4274.52,1944.09 4274.52,2184.16 4132,2326.69 4132,2572.58 3824,2880.58 3824,3279.25 3573.19,3530.06 3573.19,3799.71 3765.19,3991.71 3765.19,4266.71 3781.86,4283.37
  Top Layer w8: v2(6734.41,1825.63) U30.U11@6754.09,1845.31 ; v2@6734.41,1834.63 ccw(c6734.41,1856.36) 6749.77,1840.99 ccw(c6765.14,1825.63) v2@6743.41,1825.63 ; U30.U11@6748.25,1845.31 cw(c6734.15,1845.31) 6744.12,1835.34 cw(c6754.09,1825.37) U30.U11@6754.09,1839.47
  MidLayer2 w4: v1(4295.96,1922.66) v1@4291.48,1927.14 ; v1@4295.96,1928.16 ccw(c4295.96,1941.44) 4305.34,1932.05 ccw(c4314.73,1922.66) v1@4301.46,1922.66 ; v1@4295.96,1932.16 ccw(c4295.96,1955.1) 4312.17,1938.88 ccw(c4328.39,1922.66) v1@4305.46,1922.66 ; v2(6734.41,1825.63) 6740.27,1825.63 6760.52,1805.37 6781.86,1805.37 6792.86,1794.37 6792.86,1775.04 6801.19,1766.71 6823.86,1766.71 6832.19,1758.37 6832.19,1740.04 6844.86,1727.37 6861.19,1727.37 6871.86,1716.71 6871.86,1456.71 6848.52,1433.37 6380.19,1433.37 6363.52,1450.04 6289.96,1450.04 6214.96,1525.04 5565.8,1525.04 5408.13,1682.71 5016.47,1682.71 4726.36,1972.81 4346.1,1972.81 4300.43,1927.14 v1@4291.48,1927.14 ; v1@4291.48,1927.14 4291.36,1927.26 v1@4291.48,1927.14
HOST_SD.CLK: J29.5 U30.D11 | length 1757.9
  Top Layer w8: U30.D11@7265.91,1839.47 cw(c7265.91,1825.37) 7275.88,1835.34 cw(c7285.85,1845.31) U30.D11@7271.75,1845.31 ; U30.D11@7265.91,1845.31 v2(7285.59,1825.63) ; v2@7276.59,1825.63 ccw(c7254.86,1825.63) 7270.23,1840.99 ccw(c7285.59,1856.36) v2@7285.59,1834.63
  MidLayer1 w4: v1(7148.52,1400.04) 7187.52,1439.04 7187.52,1479.37 7198.52,1490.37 7256.86,1490.37 7265.86,1499.37 7265.86,1805.9 v2(7285.59,1825.63) ; v1@7148.52,1405.54 ccw(c7148.52,1418.82) 7157.91,1409.43 ccw(c7167.3,1400.04) v1@7154.02,1400.04 ; v1@7148.52,1409.54 ccw(c7148.52,1432.48) 7164.74,1416.26 ccw(c7180.96,1400.04) v1@7158.02,1400.04 ; v2@7274.59,1825.63 cw(c7248.03,1825.63) 7266.81,1806.85 cw(c7285.59,1788.07) v2@7285.59,1814.63 ; v2@7278.59,1825.63 cw(c7261.69,1825.63) 7273.64,1813.68 cw(c7285.59,1801.73) v2@7285.59,1818.63
  MidLayer2 w4: v1(6455.86,1393.71) 6478.86,1416.71 6902.52,1416.71 6917.19,1431.37 6942.19,1431.37 6968.56,1405 7085.04,1405 7090,1400.04 v1(7148.52,1400.04) ; v1@6455.86,1399.21 ccw(c6455.86,1412.49) 6465.25,1403.1 ccw(c6474.64,1393.71) v1@6461.36,1393.71 ; v1@6455.86,1403.21 ccw(c6455.86,1426.14) 6472.07,1409.93 ccw(c6488.29,1393.71) v1@6465.36,1393.71 ; v1@7141.81,1393.32 ccw(c7125.59,1377.11) 7125.59,1400.04 ccw(c7125.59,1422.98) v1@7141.81,1406.76 ; v1@7144.64,1396.15 ccw(c7135.25,1386.76) 7135.25,1400.04 ccw(c7135.25,1413.32) v1@7144.64,1403.93
  Bottom Layer w4: J29.5@6403.32,1404.65 6444.91,1404.65 ; J29.5@6413.6,1396.97 cw(c6428.94,1385.5) 6428.94,1404.65 cw(c6428.94,1423.8) J29.5@6413.6,1412.34 ; J29.5@6416.81,1394.57 cw(c6436.93,1379.53) 6436.93,1404.65 cw(c6436.93,1429.77) J29.5@6416.81,1414.73 ; J29.5@6420.01,1392.18 cw(c6444.91,1373.56) 6444.91,1404.65 ; J29.5@6420.01,1417.13 ccw(c6444.91,1435.74) 6444.91,1404.65 ; v1(6455.86,1393.71) 6444.91,1404.65
HOST_SD.CMD: J29.2 U30.U20 | length 433.7
  Top Layer w8: v2(6734.41,1471.3) U30.U20@6754.09,1490.98 ; v2@6734.41,1480.3 ccw(c6734.41,1502.03) 6749.77,1486.66 ccw(c6765.14,1471.3) v2@6743.41,1471.3 ; U30.U20@6748.25,1490.98 cw(c6734.15,1490.98) 6744.12,1481.01 cw(c6754.09,1471.04) U30.U20@6754.09,1485.14
  Bottom Layer w4: J29.2@6698.99,1404.65 6698.99,1435.88 v2(6734.41,1471.3) ccw(c6769.98,1435.72) J29.2@6719.78,1432.4 ; J29.2@6698.99,1443.87 ccw(c6698.99,1463.14) J29.2@6712.62,1449.51 ; J29.2@6698.99,1447.87 ccw(c6698.99,1476.8) 6719.45,1456.34 ; J29.2@6698.99,1451.87 ccw(c6698.99,1490.46) v2@6726.28,1463.17 ; J29.2@6707.81,1431.61 cw(c6734.87,1433.4) 6715.69,1452.58 ; J29.2@6711.8,1431.88 cw(c6746.58,1434.17) 6721.93,1458.82 ; J29.2@6715.79,1432.14 cw(c6758.28,1434.95) v2@6728.17,1465.06 ; 6722.46,1459.35 ccw(c6710.51,1471.3) v2@6727.41,1471.3 ; 6722.46,1459.35 cw(c6734.41,1447.4) v2@6734.41,1464.3 ; v2@6723.41,1471.3 cw(c6696.85,1471.3) 6715.63,1452.52 cw(c6734.41,1433.75) v2@6734.41,1460.3
HOST_SD.DAT0: J29.7 U30.U19 | length 1266.4
  Top Layer w8: v2(6734.41,1510.67) U30.U19@6754.09,1530.35 ; v2@6734.41,1519.67 ccw(c6734.41,1541.4) 6749.77,1526.03 ccw(c6765.14,1510.67) v2@6743.41,1510.67 ; U30.U19@6748.25,1530.35 cw(c6734.15,1530.35) 6744.12,1520.38 cw(c6754.09,1510.41) U30.U19@6754.09,1524.51
  MidLayer1 w4: v1(6578.86,1308.37) 6656.86,1308.37 6715.19,1366.71 6715.19,1491.45 6726.78,1503.04 6734.41,1503.04 v2(6734.41,1510.67) ; v1@6582.75,1304.49 cw(c6592.14,1295.1) 6592.14,1308.37 cw(c6592.14,1321.65) v1@6582.75,1312.26 ; v1@6585.57,1301.66 cw(c6601.79,1285.44) 6601.79,1308.37 cw(c6601.79,1331.31) v1@6585.57,1315.09 ; v2@6723.41,1510.67 cw(c6696.85,1510.67) 6715.63,1491.89 cw(c6734.41,1473.12) v2@6734.41,1499.67 ; v2@6727.41,1510.67 cw(c6710.51,1510.67) 6722.46,1498.72 cw(c6734.41,1486.77) v2@6734.41,1503.67
  Bottom Layer w4: J29.7@6194.89,1363.54 cw(c6159.32,1327.98) 6209.62,1327.98 cw(c6259.92,1327.98) J29.7@6224.35,1363.54 ; J29.7@6197.72,1366.37 cw(c6168.98,1337.63) 6209.62,1337.63 cw(c6250.26,1337.63) J29.7@6221.53,1366.37 ; J29.7@6200.55,1369.2 cw(c6178.64,1347.29) 6209.62,1347.29 cw(c6240.61,1347.29) J29.7@6218.7,1369.2 ; J29.7@6209.62,1404.65 6209.62,1298.75 6225,1283.37 6553.86,1283.37 v1(6578.86,1308.37) ; v1@6569.36,1308.37 cw(c6546.42,1308.37) 6562.64,1292.16 cw(c6578.86,1275.94) v1@6578.86,1298.87 ; v1@6573.36,1308.37 cw(c6560.08,1308.37) 6569.47,1298.99 cw(c6578.86,1289.6) v1@6578.86,1302.87
HOST_SD.DAT1: J29.8 U30.V19 | length 840.1
  Top Layer w8: v2(6695.04,1510.67) U30.V19@6714.72,1530.35 ; v2@6695.04,1519.67 ccw(c6695.04,1541.4) 6710.4,1526.03 ccw(c6725.77,1510.67) v2@6704.04,1510.67 ; U30.V19@6708.88,1530.35 cw(c6694.78,1530.35) 6704.75,1520.38 cw(c6714.72,1510.41) U30.V19@6714.72,1524.51
  Bottom Layer w4: J29.8@6134.45,1450.17 ccw(c6129.05,1462.69) 6142.69,1462.69 ; J29.8@6136.03,1446.49 ccw(c6131.67,1456.61) 6142.69,1456.61 ccw(c6153.71,1456.61) J29.8@6149.35,1446.49 ; J29.8@6142.69,1404.65 6142.69,1462.69 ; J29.8@6150.94,1450.17 cw(c6156.33,1462.69) 6142.69,1462.69 ; v2@6684.04,1510.67 cw(c6657.48,1510.67) 6676.26,1491.89 cw(c6695.04,1473.12) v2@6695.04,1499.67 ; v2@6688.04,1510.67 cw(c6671.14,1510.67) 6683.09,1498.72 cw(c6695.04,1486.77) v2@6695.04,1503.67 ; v2(6695.04,1510.67) 6675.41,1491.04 6374.19,1491.04 6349.86,1466.71 6146.71,1466.71 6142.69,1462.69
HOST_SD.DAT2: J29.9 U30.P20 | length 451
  Top Layer w8: v2(6852.52,1471.3) U30.P20@6872.2,1490.98 ; v2@6852.52,1480.3 ccw(c6852.52,1502.03) 6867.88,1486.66 ccw(c6883.25,1471.3) v2@6861.52,1471.3 ; U30.P20@6866.36,1490.98 cw(c6852.26,1490.98) 6862.23,1481.01 cw(c6872.2,1471.04) U30.P20@6872.2,1485.14
  Bottom Layer w4: v2@6852.52,1460.3 cw(c6852.52,1433.74) 6871.3,1452.52 cw(c6890.08,1471.3) v2@6863.52,1471.3 ; v2@6852.52,1464.3 cw(c6852.52,1447.4) 6864.47,1459.35 cw(c6876.42,1471.3) v2@6859.52,1471.3 ; v2(6852.52,1471.3) 6881.86,1441.96 6881.86,1418.64 J29.9@6895.84,1404.65 ; v2@6855.06,1468.76 ccw(c6895.84,1509.54) J29.9@6895.84,1451.87 ; 6861.89,1461.93 ccw(c6895.84,1495.89) J29.9@6895.84,1447.87 ; 6862.44,1461.38 cw(c6832.09,1431.03) J29.9@6875.01,1431.03 ; 6868.72,1455.1 ccw(c6895.84,1482.23) J29.9@6895.84,1443.87 ; 6869.27,1454.55 cw(c6845.74,1431.03) J29.9@6879.01,1431.03 ; J29.9@6875.54,1448.27 ccw(c6895.84,1468.57) J29.9@6895.84,1439.87 ; J29.9@6876.09,1447.72 cw(c6859.4,1431.03) J29.9@6883.01,1431.03
HOST_SD.DAT3: J29.1 U30.T20 | length 365.1
  Top Layer w8: v2(6773.78,1471.3) U30.T20@6793.46,1490.98 ; v2@6773.78,1480.3 ccw(c6773.78,1502.03) 6789.14,1486.66 ccw(c6804.51,1471.3) v2@6782.78,1471.3 ; U30.T20@6787.62,1490.98 cw(c6773.52,1490.98) 6783.49,1481.01 cw(c6793.46,1471.04) U30.T20@6793.46,1485.14
  Bottom Layer w4: v2@6773.78,1460.3 cw(c6773.78,1433.74) 6792.56,1452.52 cw(c6811.34,1471.3) v2@6784.78,1471.3 ; v2@6773.78,1464.3 cw(c6773.78,1447.4) 6785.73,1459.35 ; v2(6773.78,1471.3) 6797.42,1447.66 J29.1@6797.42,1404.65 ; v2@6775.35,1469.73 cw(c6749.19,1443.57) J29.1@6785,1434.26 ; v2@6780.29,1464.79 cw(c6757.03,1441.53) J29.1@6788.87,1433.25 ; v2@6780.78,1471.3 ccw(c6797.68,1471.3) 6785.73,1459.35 ; 6785.23,1459.85 cw(c6764.88,1439.49) J29.1@6792.74,1432.25 ; 6790.17,1454.9 cw(c6772.72,1437.45) J29.1@6796.61,1431.24 ; 6790.24,1454.84 ccw(c6797.42,1462.02) J29.1@6797.42,1451.87
HOST_SD.DETECT: U30.Y17 U66.4 | length 2029.9
  Top Layer w8: v2(6616.3,1589.41) U30.Y17@6635.98,1609.09 ; v2@6616.3,1598.41 ccw(c6616.3,1620.14) 6631.66,1604.77 ccw(c6647.03,1589.41) v2@6625.3,1589.41 ; U30.Y17@6630.14,1609.09 cw(c6616.04,1609.09) 6626.01,1599.12 cw(c6635.98,1589.15) U30.Y17@6635.98,1603.25
  MidLayer1 w4: v1@6531.86,1658.21 cw(c6531.86,1648.15) 6538.97,1655.26 ; v1(6531.86,1667.71) 6531.86,1662.37 6578.12,1616.11 6589.6,1616.11 v2(6616.3,1589.41) ; v1@6533.36,1667.71 ccw(c6549.85,1667.71) 6538.19,1656.04 ; v1@6537.36,1667.71 ccw(c6563.51,1667.71) 6545.02,1649.21 ; v1@6541.36,1667.71 ccw(c6577.17,1667.71) 6551.85,1642.39
  MidLayer2 w4: v1@5149.76,1776.81 cw(c5165.61,1760.96) 5165.61,1783.37 ; v1(5151.52,1775.04) 5159.86,1783.37 5576.63,1783.37 5684.96,1675.04 6524.52,1675.04 v1(6531.86,1667.71) ; v1@5152.58,1773.98 cw(c5175.27,1751.3) 5175.27,1783.37 ; v1@5155.41,1771.15 cw(c5184.92,1741.64) 5184.92,1783.37 ; v1@5158.24,1768.32 cw(c5194.58,1731.99) 5194.58,1783.37 ; 6491.22,1675.04 cw(c6491.22,1627.07) v1@6525.14,1660.99 ; 6500.88,1675.04 cw(c6500.88,1636.73) v1@6527.97,1663.82 ; 6510.53,1675.04 cw(c6510.53,1646.38) v1@6530.8,1666.65 ; 6520.19,1675.04 cw(c6520.19,1656.04) v1@6533.62,1669.48
  Bottom Layer w4: v1(5151.52,1775.04) 5189.96,1775.04 5219.88,1745.12 U66.4@5242.6,1745.12
HOST_SD.PROTECT: U30.W20 U65.4 | length 2643
  Top Layer w8: v2(6655.67,1471.3) U30.W20@6675.35,1490.98 ; v2@6655.67,1480.3 ccw(c6655.67,1502.03) 6671.03,1486.66 ccw(c6686.4,1471.3) v2@6664.67,1471.3 ; U30.W20@6669.51,1490.98 cw(c6655.41,1490.98) 6665.38,1481.01 cw(c6675.35,1471.04) U30.W20@6675.35,1485.14
  MidLayer1 w4: v1@6633.47,1333.43 ccw(c6597.14,1369.76) 6648.52,1369.76 ; v1@6636.3,1330.6 ccw(c6606.79,1360.11) 6648.52,1360.11 ; v1@6639.13,1327.77 ccw(c6616.45,1350.45) 6648.52,1350.45 ; v1(6640.19,1326.71) 6648.52,1335.04 6648.52,1471.3 v2(6655.67,1471.3) ; v1@6641.96,1324.94 ccw(c6626.11,1340.79) 6648.52,1340.79 ; 6648.52,1427.49 cw(c6699.48,1427.49) v2@6663.45,1463.52 ; 6648.52,1437.15 cw(c6689.82,1437.15) v2@6660.62,1466.35 ; 6648.52,1446.81 cw(c6680.16,1446.81) v2@6657.79,1469.18 ; 6648.52,1456.46 cw(c6670.51,1456.46) v2@6654.96,1472.01
  Bottom Layer w4: U65.4@5235.66,1454.4 cw(c5218.91,1437.65) 5242.6,1437.65 cw(c5266.28,1437.65) U65.4@5249.54,1454.4 ; U65.4@5238.49,1457.23 cw(c5228.57,1447.31) 5242.6,1447.31 cw(c5256.63,1447.31) U65.4@5246.71,1457.23 ; U65.4@5242.6,1465.12 5242.6,1435.04 5244.26,1433.37 5511.86,1433.37 5528.52,1450.04 5528.52,1500.04 5536.86,1508.37 5803.88,1508.37 6006.86,1305.39 6006.86,1211.36 6018.5,1199.71 6410.29,1199.71 6420,1190 6420,992.71 6430,982.71 6457.23,982.71 6555,1080.48 6555,1241.52 v1(6640.19,1326.71)
HOST_SRAM.A0: U30.F4 U47.1 | length 1654.4
  Top Layer w4: v1(7511.86,3366.71) 7512.86,3365.71 U47.1@7555.59,3365.71 ; v1@7515.75,3370.6 ccw(c7527.54,3382.4) 7527.54,3365.71 ; v1@7518.57,3359.99 cw(c7532.38,3346.18) U47.1@7532.38,3365.71 ; v1@7518.57,3373.43 ccw(c7537.2,3392.05) U47.1@7537.2,3365.71 ; U47.1@7532.37,3360.05 ccw(c7518.72,3346.4) 7518.72,3365.71 ccw(c7518.72,3385.02) U47.1@7532.37,3371.37
  Top Layer w8: U30.F4@7187.17,2120.91 v2(7206.85,2140.59) ; U30.F4@7187.17,2126.75 ccw(c7187.17,2140.85) 7197.14,2130.88 ccw(c7207.11,2120.91) U30.F4@7193.01,2120.91 ; v2@7197.85,2140.59 cw(c7176.12,2140.59) 7191.49,2125.23 cw(c7206.85,2109.86) v2@7206.85,2131.59
  MidLayer1 w4: v2@7195.85,2140.59 ccw(c7169.29,2140.59) 7188.07,2159.37 ccw(c7206.85,2178.15) v2@7206.85,2151.59 ; v2@7199.85,2140.59 ccw(c7182.95,2140.59) 7194.9,2152.54 ccw(c7206.85,2164.49) v2@7206.85,2147.59 ; v2(7206.85,2140.59) 7187.19,2160.25 7187.19,2334.35 7465.19,2612.35 7465.19,2791.71 7523.52,2850.04 7523.52,3319.69 7511.86,3331.35 v1(7511.86,3366.71)
HOST_SRAM.A1: U30.E1 U47.2 | length 1700.2
  Top Layer w4: U47.2@7555.59,3334.21 v1@7590.86,3334.21 ; U47.2@7574.56,3334.21 cw(c7574.56,3308.41) v1@7592.81,3326.66 ; U47.2@7578.61,3334.21 ccw(c7578.61,3354.28) v1@7592.81,3340.09 ; U47.2@7579.15,3328.93 cw(c7590.86,3318.62) v1@7590.86,3334.21 ; U47.2@7579.15,3339.5 ccw(c7590.86,3349.81) v1@7590.86,3334.21 ; 7584.22,3334.21 cw(c7584.22,3318.07) v1@7595.64,3329.49 ; v1(7599.52,3333.37) 7591.7,3333.37 v1@7590.86,3334.21
  Top Layer w8: U30.E1@7226.54,2239.02 v2(7246.22,2258.7) ; U30.E1@7226.54,2244.86 ccw(c7226.54,2258.96) 7236.51,2248.99 ccw(c7246.48,2239.02) U30.E1@7232.38,2239.02 ; v2@7237.22,2258.7 cw(c7215.49,2258.7) 7230.86,2243.34 cw(c7246.22,2227.97) v2@7246.22,2249.7
  MidLayer2 w4: v2@7238.44,2266.48 ccw(c7219.66,2285.26) 7246.22,2285.26 ccw(c7272.78,2285.26) v2@7254,2266.48 ; v2@7241.27,2263.65 ccw(c7229.32,2275.6) 7246.22,2275.6 ccw(c7263.12,2275.6) v2@7251.17,2263.65 ; v2(7246.22,2258.7) 7246.22,2300.07 7305.65,2359.5 7440.19,2494.04 7440.19,2701.04 7647.52,2908.37 7698.52,2908.37 7706.86,2916.71 7706.86,3280.04 7653.52,3333.37 v1(7599.52,3333.37) ; v1@7603.41,3329.49 cw(c7612.8,3320.1) 7612.8,3333.37 cw(c7612.8,3346.65) v1@7603.41,3337.26 ; v1@7606.24,3326.66 cw(c7622.46,3310.44) 7622.46,3333.37 cw(c7622.46,3356.31) v1@7606.24,3340.09
HOST_SRAM.A2: U30.E3 U47.3 | length 1732.5
  Top Layer w4: v1(7397.19,2633.37) 7433.37,2633.37 7457.19,2657.19 7457.19,2846.73 7423.52,2880.39 7423.52,3075.04 7440.19,3091.71 7465.19,3091.71 7481.86,3075.04 7490.19,3075.04 7506.86,3091.71 7506.86,3286.05 7523.52,3302.72 ; v1@7401.08,2629.49 cw(c7410.47,2620.1) 7410.47,2633.37 cw(c7410.47,2646.65) v1@7401.08,2637.26 ; v1@7403.91,2626.66 cw(c7420.13,2610.44) 7420.13,2633.37 cw(c7420.13,2656.31) v1@7403.91,2640.09 ; U47.3@7531.27,3298.45 ccw(c7523.52,3293.56) 7523.52,3302.72 ; U47.3@7531.27,3306.99 cw(c7523.52,3311.87) 7523.52,3302.72 ; U47.3@7555.59,3302.72 7523.52,3302.72
  Top Layer w8: U30.E3@7226.54,2160.28 v2(7246.22,2179.96) ; U30.E3@7226.54,2166.12 ccw(c7226.54,2180.22) 7236.51,2170.25 ccw(c7246.48,2160.28) U30.E3@7232.38,2160.28 ; v2@7237.22,2179.96 cw(c7215.49,2179.96) 7230.86,2164.6 cw(c7246.22,2149.23) v2@7246.22,2170.96
  MidLayer2 w4: 7226.83,2211.74 cw(c7196.83,2181.74) v2@7239.23,2180.21 ; 7233.32,2205.24 cw(c7209.37,2181.29) v2@7243.22,2180.07 ; 7239.82,2198.75 cw(c7221.91,2180.84) v2@7247.22,2179.92 ; v2(7246.22,2179.96) 7246.22,2192.34 7226.52,2212.04 7226.52,2378.71 7390.19,2542.37 7390.19,2626.37 v1(7397.19,2633.37) ; 7390.19,2593.54 cw(c7437.02,2593.54) v1@7403.91,2626.66 ; 7390.19,2603.2 cw(c7427.37,2603.2) v1@7401.08,2629.49 ; 7390.19,2612.85 cw(c7417.71,2612.85) v1@7398.25,2632.31 ; 7390.19,2622.51 cw(c7408.05,2622.51) v1@7395.42,2635.14
HOST_SRAM.A3: U30.F8 U47.4 | length 2431.7
  Top Layer w4: U47.4@7555.59,3271.22 7608.38,3271.22 7673.52,3206.08 7673.52,3052.37 7631.86,3010.71 7631.86,2933.37 7740.19,2825.04 7740.19,2525.04 7756.86,2508.37 7756.86,2081.71 7680.07,2004.93 ; U47.4@7578.81,3265.56 cw(c7592.46,3251.91) 7592.46,3271.22 cw(c7592.46,3290.53) U47.4@7578.81,3276.88 ; v1@7585,1980.23 7655.23,1980.23 7680,2005 ; v1@7588.89,1976.11 cw(c7598.84,1966.16) 7598.84,1980.23 ; v1@7588.89,1983.89 ccw(c7597.72,1992.72) 7597.72,1980.23 ; v1@7591.72,1973.28 cw(c7608.5,1956.5) 7608.5,1980.23 ; v1@7591.72,1986.72 ccw(c7607.37,2002.37) 7607.37,1980.23
  Top Layer w8: U30.F8@7187.17,1963.43 v2(7206.85,1983.11) ; U30.F8@7187.17,1969.27 ccw(c7187.17,1983.37) 7197.14,1973.4 ccw(c7207.11,1963.43) U30.F8@7193.01,1963.43 ; v2@7197.85,1983.11 cw(c7176.12,1983.11) 7191.49,1967.75 cw(c7206.85,1952.38) v2@7206.85,1974.11
  MidLayer1 w4: v2(7206.85,1983.11) 7187.52,1963.78 7187.52,1933.37 7197.52,1923.37 7295.52,1923.37 7305.19,1913.71 7305.19,1891.71 7313.69,1883.2 7315.97,1883.2 7330.54,1868.63 7349.39,1868.63 7351.31,1866.71 7488.54,1866.71 7527.75,1827.5 7562.5,1827.5 7582.5,1847.5 7582.5,1932.5 7585,1935 v1(7585,1980) ; v1@7578.28,1973.28 cw(c7562.06,1957.06) 7585,1957.06 cw(c7607.94,1957.06) v1@7591.72,1973.28 ; v1@7581.11,1976.11 cw(c7571.72,1966.72) 7585,1966.72 cw(c7598.28,1966.72) v1@7588.89,1976.11
HOST_SRAM.A4: U30.D1 U47.5 | length 1480
  Top Layer w4: U47.5@7555.59,3239.72 v1(7600.52,3239.71) ; U47.5@7577.55,3239.72 cw(c7577.55,3216.73) v1@7593.81,3232.99 ; U47.5@7577.63,3239.72 ccw(c7577.63,3262.6) v1@7593.81,3246.43 ; U47.5@7578.81,3234.07 cw(c7592.46,3220.41) 7592.46,3239.72 cw(c7592.46,3259.04) U47.5@7578.81,3245.38 ; 7587.21,3239.72 cw(c7587.21,3226.39) v1@7596.64,3235.82 ; 7587.28,3239.72 ccw(c7587.28,3252.95) v1@7596.64,3243.6
  Top Layer w8: U30.D1@7265.91,2239.02 v2(7285.59,2258.7) ; U30.D1@7265.91,2244.86 ccw(c7265.91,2258.96) 7275.88,2248.99 ccw(c7285.85,2239.02) U30.D1@7271.75,2239.02 ; v2@7276.59,2258.7 cw(c7254.86,2258.7) 7270.23,2243.34 cw(c7285.59,2227.97) v2@7285.59,2249.7
  MidLayer1 w4: v2@7277.81,2266.48 ccw(c7259.03,2285.26) 7285.59,2285.26 ccw(c7312.15,2285.26) v2@7293.37,2266.48 ; v2@7280.64,2263.65 ccw(c7268.69,2275.6) 7285.59,2275.6 ; v2(7285.59,2258.7) 7285.59,2371.79 7297.5,2383.71 7343.71,2383.71 7490.19,2530.19 7490.19,2782.77 7548.52,2841.1 7548.52,3187.71 v1(7600.52,3239.71) ; 7285.59,2275.6 ccw(c7302.49,2275.6) v2@7290.54,2263.65 ; v1@7591.02,3239.71 cw(c7568.09,3239.71) 7584.31,3223.49 cw(c7600.52,3207.27) v1@7600.52,3230.21 ; v1@7595.02,3239.71 cw(c7581.75,3239.71) 7591.14,3230.32 cw(c7600.52,3220.93) v1@7600.52,3234.21
HOST_SRAM.A5: U30.B1 U47.18 | length 1087.4
  Top Layer w4: U47.18@7555.59,2830.28 7591.15,2830.28 ; U47.18@7579.09,2824.92 cw(c7591.15,2814.03) 7591.15,2830.28 ; U47.18@7579.09,2835.64 ccw(c7591.15,2846.53) 7591.15,2830.28 ; v1@7683.47,2556.76 ccw(c7667.26,2572.98) 7690.19,2572.98 ccw(c7713.13,2572.98) v1@7696.91,2556.76 ; v1@7686.3,2553.93 ccw(c7676.91,2563.32) 7690.19,2563.32 ccw(c7703.47,2563.32) v1@7694.08,2553.93 ; v1(7690.19,2550.04) 7690.19,2731.23 7591.15,2830.28
  Top Layer w8: U30.B1@7344.65,2239.02 v2(7364.33,2258.7) ; U30.B1@7344.65,2244.86 ccw(c7344.65,2258.96) 7354.62,2248.99 ccw(c7364.59,2239.02) U30.B1@7350.49,2239.02 ; v2@7355.33,2258.7 cw(c7333.6,2258.7) 7348.97,2243.34 cw(c7364.33,2227.97) v2@7364.33,2249.7
  Bottom Layer w4: v2(7364.33,2258.7) 7382.99,2277.35 ; v2@7364.36,2265.7 ccw(c7364.44,2282.33) 7376.2,2270.57 ccw(c7387.96,2258.81) v2@7371.33,2258.73 ; v2@7364.38,2269.7 ccw(c7364.51,2295.83) 7382.98,2277.35 ; v2@7375.33,2258.75 cw(c7401.46,2258.88) 7382.98,2277.35 ; v1@7682.98,2543.86 ccw(c7669.53,2532.31) 7669.53,2550.04 ; v1@7682.98,2556.23 cw(c7669.53,2567.77) 7669.53,2550.04 ; v1@7686.02,2546.46 ccw(c7678.23,2539.78) 7678.23,2550.04 ccw(c7678.23,2560.3) v1@7686.02,2553.62 ; v1(7690.19,2550.04) 7669.52,2550.04 ; 7382.99,2277.35 7384.17,2277.35 7398.52,2291.71 7411.19,2291.71 7669.52,2550.04
HOST_SRAM.A6: U30.C4 U47.19 | length 994.7
  Top Layer w4: U47.19@7555.59,2798.78 7583.79,2798.78 ; U47.19@7573.15,2798.78 cw(c7577.47,2785.94) 7587.05,2795.52 ; U47.19@7574.42,2794.99 cw(c7579.76,2779.11) v1@7591.61,2790.95 ; U47.19@7580.84,2796.56 cw(c7583.78,2795.71) 7583.78,2798.78 ; U47.19@7580.84,2801 ccw(c7583.78,2801.85) 7583.78,2798.78 ; v1(7599.86,2791.71) 7590.86,2791.71 7583.79,2798.78
  Top Layer w8: U30.C4@7305.28,2120.91 v2(7324.96,2140.59) ; U30.C4@7305.28,2126.75 ccw(c7305.28,2140.85) 7315.25,2130.88 ccw(c7325.22,2120.91) U30.C4@7311.12,2120.91 ; v2@7315.96,2140.59 cw(c7294.23,2140.59) 7309.6,2125.23 cw(c7324.96,2109.86) v2@7324.96,2131.59
  MidLayer1 w4: v2(7324.96,2140.59) 7344.19,2159.82 7344.19,2270 7344.19,2272.04 7344.19,2303.39 7506.86,2466.06 7506.86,2556.71 7556.86,2606.71 7556.86,2716.71 7599.86,2759.71 v1(7599.86,2791.71) ; v1@7593.14,2784.99 cw(c7576.92,2768.77) 7599.86,2768.77 cw(c7622.79,2768.77) v1@7606.57,2784.99 ; v1@7595.97,2787.82 cw(c7586.58,2778.43) 7599.86,2778.43 cw(c7613.14,2778.43) v1@7603.75,2787.82
HOST_SRAM.A7: U30.B2 U47.20 | length 1182.2
  Top Layer w4: U47.20@7555.59,2767.28 7622.95,2767.28 v1(7665.19,2725.04) ; U47.20@7578.81,2761.63 cw(c7592.46,2747.97) 7592.46,2767.28 cw(c7592.46,2786.6) U47.20@7578.81,2772.94 ; v1@7655.69,2725.04 ccw(c7632.76,2725.04) 7648.97,2741.26 ccw(c7665.19,2757.48) v1@7665.19,2734.54 ; v1@7659.69,2725.04 ccw(c7646.41,2725.04) 7655.8,2734.43 ccw(c7665.19,2743.82) v1@7665.19,2730.54
  Top Layer w8: U30.B2@7344.65,2199.65 v2(7364.33,2219.33) ; U30.B2@7344.65,2205.49 ccw(c7344.65,2219.59) 7354.62,2209.62 ccw(c7364.59,2199.65) U30.B2@7350.49,2199.65 ; v2@7355.33,2219.33 cw(c7333.6,2219.33) 7348.97,2203.97 cw(c7364.33,2188.6) v2@7364.33,2210.33
  MidLayer2 w4: v2@7353.33,2219.33 ccw(c7326.77,2219.33) 7345.55,2238.11 ccw(c7364.33,2256.89) v2@7364.33,2230.33 ; v2@7357.33,2219.33 ccw(c7340.43,2219.33) 7352.38,2231.28 ccw(c7364.33,2243.23) v2@7364.33,2226.33 ; v2(7364.33,2219.33) 7345.19,2238.47 7345.19,2268.37 7360.19,2283.37 7403.52,2283.37 7498.52,2378.37 7498.52,2683.37 7556.86,2741.71 7648.52,2741.71 v1(7665.19,2725.04) ; v1@7655.69,2725.04 ccw(c7632.76,2725.04) 7648.97,2741.26 ccw(c7665.19,2757.48) v1@7665.19,2734.54 ; v1@7659.69,2725.04 ccw(c7646.41,2725.04) 7655.8,2734.43 ccw(c7665.19,2743.82) v1@7665.19,2730.54
HOST_SRAM.A8: U30.C5 U47.21 | length 1233.5
  Top Layer w4: U47.21@7555.59,2735.79 7586.11,2735.79 ; U47.21@7580.3,2732.2 cw(c7586.11,2729.29) 7586.11,2735.79 ; U47.21@7580.3,2739.37 ccw(c7586.11,2742.29) 7586.11,2735.79 ; v1@7605.69,2706.71 ccw(c7582.76,2706.71) 7598.97,2722.93 ccw(c7615.19,2739.14) v1@7615.19,2716.21 ; v1@7609.69,2706.71 ccw(c7596.41,2706.71) 7605.8,2716.1 ccw(c7615.19,2725.49) v1@7615.19,2712.21 ; v1(7615.19,2706.71) 7586.11,2735.79
  Top Layer w8: U30.C5@7305.28,2081.54 v2(7324.96,2101.22) ; U30.C5@7305.28,2087.38 ccw(c7305.28,2101.48) 7315.25,2091.51 ccw(c7325.22,2081.54) U30.C5@7311.12,2081.54 ; v2@7315.96,2101.22 cw(c7294.23,2101.22) 7309.6,2085.86 cw(c7324.96,2070.49) v2@7324.96,2092.22
  MidLayer1 w4: v2(7324.96,2101.22) 7345.19,2121.45 7345.19,2148.71 7357.19,2160.71 7431.86,2160.71 7448.52,2177.37 7448.52,2298.04 7480.48,2330 v1(7540,2330) ; v1@7533.28,2323.28 ccw(c7517.06,2307.06) 7517.06,2330 ccw(c7517.06,2352.93) v1@7533.28,2336.72 ; v1@7536.11,2326.11 ccw(c7526.72,2316.72) 7526.72,2330 ccw(c7526.72,2343.28) v1@7536.11,2333.89
  MidLayer2 w4: v1(7540,2330) 7537.82,2330 7532.86,2325.04 7538.91,2331.09 7558.19,2350.37 7558.19,2436.37 7640.19,2518.37 7640.19,2681.71 v1(7615.19,2706.71) ; v1@7540,2339.5 ccw(c7540,2357.16) 7552.49,2344.67 ; v1@7545.5,2330 cw(c7564.05,2330) 7550.93,2343.12 ; v1@7549.5,2330 cw(c7577.71,2330) 7557.76,2349.95 ; v1@7615.19,2697.21 cw(c7615.19,2674.27) 7631.41,2690.49 cw(c7647.63,2706.71) v1@7624.69,2706.71 ; v1@7615.19,2701.21 cw(c7615.19,2687.93) 7624.58,2697.32 cw(c7633.97,2706.71) v1@7620.69,2706.71
HOST_SRAM.A9: U30.B3 U47.22 | length 1098.3
  Top Layer w4: v1@7516.02,2632.04 ccw(c7493.09,2632.04) 7509.31,2648.26 ccw(c7525.52,2664.48) v1@7525.52,2641.54 ; v1@7520.02,2632.04 ccw(c7506.75,2632.04) 7516.14,2641.43 ccw(c7525.52,2650.82) v1@7525.52,2637.54 ; v1(7525.52,2632.04) 7506.86,2650.71 7506.86,2692.04 7519.11,2704.29 ; U47.22@7532.29,2698.72 ccw(c7519.11,2685.91) 7519.11,2704.29 ; U47.22@7532.29,2709.87 cw(c7519.11,2722.67) 7519.11,2704.29 ; U47.22@7555.59,2704.29 7519.11,2704.29
  Top Layer w8: U30.B3@7344.65,2160.28 v2(7364.33,2179.96) ; U30.B3@7344.65,2166.12 ccw(c7344.65,2180.22) 7354.62,2170.25 ccw(c7364.59,2160.28) U30.B3@7350.49,2160.28 ; v2@7355.33,2179.96 cw(c7333.6,2179.96) 7348.97,2164.6 cw(c7364.33,2149.23) v2@7364.33,2170.96
  MidLayer1 w4: v2(7364.33,2179.96) 7384.41,2200.04 7415.19,2200.04 7423.52,2208.37 7423.52,2371.41 7531.86,2479.75 v1(7531.86,2510.71) ; v2@7364.33,2186.96 ccw(c7364.33,2203.86) 7376.28,2191.91 ccw(c7388.23,2179.96) v2@7371.33,2179.96 ; v2@7364.33,2190.96 ccw(c7364.33,2217.52) 7383.11,2198.74 ccw(c7401.89,2179.96) v2@7375.33,2179.96 ; v1@7525.14,2503.99 cw(c7508.92,2487.77) 7531.86,2487.77 cw(c7554.79,2487.77) v1@7538.57,2503.99 ; v1@7527.97,2506.82 cw(c7518.58,2497.43) 7531.86,2497.43 cw(c7545.14,2497.43) v1@7535.75,2506.82
  MidLayer2 w4: v1@7518.81,2625.32 cw(c7487.3,2593.82) 7531.86,2593.82 ; v1@7521.64,2628.15 cw(c7496.96,2603.47) 7531.86,2603.47 ; v1@7524.46,2630.98 cw(c7506.61,2613.13) 7531.86,2613.13 ; v1@7525.14,2517.43 ccw(c7508.92,2533.64) 7531.86,2533.64 ccw(c7554.79,2533.64) v1@7538.57,2517.43 ; v1(7525.52,2632.04) 7531.86,2625.71 v1(7531.86,2510.71) ; v1@7527.97,2514.6 ccw(c7518.58,2523.99) 7531.86,2523.99 ccw(c7545.14,2523.99) v1@7535.75,2514.6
